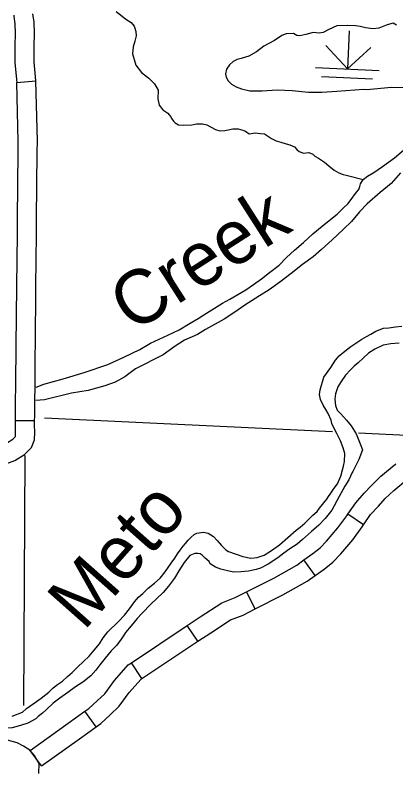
# Model space of a CAD drawing. Extents: x 1196286 to 1268366, y 2040822 to 2082115.
# Drawn here: x 1232639 to 1233761, y 2054453 to 2056680 of the extents above; entities that cross this region are included whole.
import ezdxf

# ---------------------------------------------------------------- set-up
doc = ezdxf.new("R2010")
doc.units = 0
for name, color, linetype in [('60', 7, 'Continuous'), ('61', 7, 'Continuous'), ('62', 7, 'Continuous'), ('Level 72', 7, 'Continuous'), ('Level 73', 7, 'Continuous'), ('Level 74', 7, 'Continuous'), ('Level 87', 7, 'Continuous')]:
    doc.layers.add(name, color=color, linetype=linetype)

msp = doc.modelspace()

# ---------------------------------------------------------------- linework, layer by layer
at = {"layer": '60'}
for points in [[(1232725.8, 2055495.4), (1233573.5, 2055454.6)], [(1233650.7, 2055450.9), (1234054.7, 2055431.4)], [(1232667.8, 2055384.5), (1232663.4, 2054648.3)]]:
    msp.add_lwpolyline(points, dxfattribs=at)
at = {"layer": '61'}
for p, q in [((1232643.7, 2056481.6), (1232699.7, 2056486.7)), ((1232696.5, 2055486.6), (1232640.2, 2055486.5)), ((1233665.6, 2055180), (1233619.2, 2055211.9)), ((1233522.7, 2055031.3), (1233489.9, 2055077)), ((1233346.3, 2054932.7), (1233321, 2054983)), ((1233177.4, 2054837.6), (1233146.1, 2054884.4)), ((1233012.7, 2054727.6), (1232981.5, 2054774.4)), ((1232877.4, 2054585.9), (1232844.7, 2054631.6)), ((1232716.2, 2054470.8), (1232683.5, 2054516.7))]:
    msp.add_line(p, q, dxfattribs=at)
for points in [[(1232634.9, 2056679.9), (1232635.1, 2056676.4), (1232638.5, 2056654.6), (1232639.5, 2056625.8), (1232638.6, 2056590.3), (1232638.3, 2056539.8), (1232643.7, 2056481.6)], [(1232699.7, 2056486.7), (1232694.6, 2056542.2), (1232694.9, 2056589.5), (1232695.7, 2056626.1), (1232694.6, 2056659.9), (1232691.1, 2056682.4), (1232691, 2056683.3)], [(1232528, 2055367.5), (1232529.4, 2055367.4), (1232550.4, 2055361.4), (1232577.7, 2055356.9), (1232607.1, 2055358.1), (1232638.3, 2055369.8), (1232666.7, 2055387.6), (1232687.7, 2055407.6), (1232695.6, 2055430.8), (1232696.6, 2055453.1), (1232696.5, 2055474)], [(1232530.4, 2055423.7), (1232538.5, 2055423.3), (1232562.8, 2055416.3), (1232581.1, 2055413.3), (1232595.8, 2055413.9), (1232613.2, 2055420.5), (1232632, 2055432.3), (1232639, 2055438.9), (1232639.8, 2055441.3), (1232640.3, 2055454.2), (1232640.3, 2055473.8)], [(1232640.3, 2055473.8), (1232640.2, 2055486.5)], [(1232696.5, 2055474), (1232696.5, 2055486.6)], [(1233619.2, 2055211.9), (1233642.2, 2055245.3), (1233667.6, 2055273), (1233688.5, 2055296.3), (1233716.7, 2055323.6), (1233760.6, 2055360)], [(1233665.6, 2055180), (1233686.3, 2055210.2), (1233709.3, 2055235.2), (1233729, 2055257.3), (1233754.3, 2055281.6), (1233796.6, 2055316.7)], [(1233489.9, 2055077), (1233515.6, 2055095.5), (1233537.5, 2055112.1), (1233556.4, 2055132.1), (1233589.9, 2055171.3), (1233615.7, 2055206.7), (1233619.2, 2055211.9)], [(1233522.7, 2055031.3), (1233549, 2055050.2), (1233575.3, 2055070.1), (1233598.3, 2055094.5), (1233634.1, 2055136.4), (1233661.6, 2055174.2), (1233665.6, 2055180)], [(1233321, 2054983), (1233401.5, 2055023.6), (1233468.9, 2055061.9), (1233489.9, 2055077)], [(1233346.3, 2054932.7), (1233428.1, 2054974), (1233499.3, 2055014.5), (1233522.7, 2055031.3)], [(1233146.1, 2054884.4), (1233184.3, 2054909.8), (1233247.9, 2054950.7), (1233287.6, 2054966.1), (1233321, 2054983)], [(1233177.4, 2054837.6), (1233215.1, 2054862.8), (1233273.5, 2054900.3), (1233310.5, 2054914.7), (1233346.3, 2054932.7)], [(1232981.5, 2054774.4), (1233146.1, 2054884.4)], [(1233012.7, 2054727.6), (1233177.4, 2054837.6)], [(1232844.7, 2054631.6), (1232856.4, 2054640), (1232881, 2054661.9), (1232903.1, 2054683.2), (1232931.3, 2054722.5), (1232971.8, 2054768), (1232981.5, 2054774.4)], [(1232877.4, 2054585.9), (1232891.5, 2054596), (1232919.3, 2054620.7), (1232945.8, 2054646.2), (1232975.3, 2054687.3), (1233009, 2054725.2), (1233012.7, 2054727.6)], [(1232683.5, 2054516.7), (1232795.5, 2054596.5), (1232844.7, 2054631.6)], [(1232716.2, 2054470.8), (1232828.2, 2054550.7), (1232877.4, 2054585.9)]]:
    msp.add_lwpolyline(points, dxfattribs=at)
at = {"layer": '62'}
for points in [[(1232936.7, 2056691.1), (1232954.8, 2056677.3), (1232964.8, 2056668.5), (1232980.4, 2056658.1), (1232989.7, 2056647.5), (1232990.7, 2056644.1), (1232994.3, 2056631.6), (1232995.3, 2056619.2), (1232992.1, 2056603.4), (1232987, 2056586.2), (1232984.8, 2056565.6), (1232994.1, 2056532.7), (1233011.4, 2056511.4), (1233032.9, 2056494.2), (1233049.5, 2056478.2), (1233060.5, 2056459.6), (1233059.8, 2056433.3), (1233063.7, 2056415.5), (1233074, 2056401.5), (1233088.8, 2056391.1), (1233096.9, 2056381.2), (1233101, 2056374.4), (1233105.4, 2056368.3), (1233110.2, 2056363), (1233120.2, 2056357.2), (1233133.7, 2056355.9), (1233159.5, 2056357.1), (1233174.2, 2056359.9), (1233191, 2056360.4), (1233203.7, 2056357.6), (1233216.8, 2056350.6), (1233229.4, 2056343.7), (1233242.1, 2056339.7), (1233256.3, 2056340.3), (1233266.8, 2056342.4), (1233280, 2056345.6), (1233284.5, 2056345.5), (1233296.5, 2056345.8), (1233309.9, 2056341.8), (1233317.7, 2056338.3), (1233328.9, 2056330.3), (1233346.5, 2056333.4), (1233361.8, 2056331.7), (1233373.4, 2056330.8), (1233385.7, 2056323.1), (1233394.2, 2056317.3), (1233407.6, 2056310.4), (1233421.4, 2056306.4), (1233437.1, 2056301.7), (1233447.9, 2056298.5), (1233461.7, 2056292.3), (1233468.7, 2056284.7), (1233475.4, 2056278.6), (1233488.4, 2056273.5), (1233503.8, 2056275.6), (1233515.7, 2056271.3), (1233522, 2056265.2), (1233532.4, 2056259), (1233550.2, 2056247.8), (1233562.8, 2056236.4), (1233578.8, 2056223.8), (1233592.9, 2056216), (1233605.6, 2056211.4)], [(1232700.5, 2055585.7), (1232724, 2055593.7), (1232780.4, 2055609.8), (1232842.1, 2055628.5), (1232911.7, 2055652), (1232958.9, 2055673.9), (1233006.4, 2055696.6), (1233037.7, 2055714.9), (1233063.3, 2055726.2), (1233088.6, 2055738.3), (1233122.5, 2055754), (1233155, 2055773.5), (1233178.4, 2055787.8), (1233195, 2055797.7), (1233249.5, 2055832.7), (1233271.3, 2055844.1), (1233295.5, 2055857.7), (1233318.9, 2055872), (1233341.6, 2055887.8), (1233365, 2055904.1), (1233388.5, 2055922.5), (1233416.9, 2055944.7), (1233438.9, 2055966.6), (1233461.7, 2055988.5), (1233488.2, 2056011.4), (1233516.3, 2056036.6), (1233543.9, 2056059.2), (1233564.4, 2056075.8), (1233587.5, 2056094.7), (1233604.2, 2056111), (1233619.8, 2056125.4), (1233633.9, 2056144.4), (1233644.9, 2056159.3), (1233651.4, 2056166.7), (1233654.2, 2056175.7), (1233656.1, 2056183.6), (1233664.2, 2056196.3), (1233677.4, 2056206.6), (1233695.5, 2056217.3), (1233720.9, 2056235), (1233756.1, 2056260), (1233783, 2056282.6)], [(1233773.8, 2056216.2), (1233747.2, 2056184.6), (1233714.2, 2056157.6), (1233675.9, 2056124.6), (1233653.5, 2056101.6), (1233629.5, 2056073), (1233605.2, 2056048.9), (1233573, 2056018.5), (1233541.1, 2055990.4), (1233516.5, 2055968.9), (1233485.9, 2055946.4), (1233451.8, 2055919.4), (1233418.5, 2055894.7), (1233387.8, 2055871.8), (1233358.4, 2055854.1), (1233316, 2055826.2), (1233286.2, 2055806.3), (1233255.2, 2055785.6), (1233200.1, 2055754.8), (1233176.7, 2055740.5), (1233138.2, 2055723.3), (1233110.6, 2055706.4), (1233075.5, 2055680.9), (1232993.2, 2055639.2), (1232962.6, 2055615.2), (1232933.5, 2055600.2), (1232903, 2055588.9), (1232854.1, 2055575.3), (1232805, 2055567.4), (1232725.7, 2055548.5), (1232700.2, 2055546)], [(1233605.6, 2056211.4), (1233614.1, 2056209), (1233621.6, 2056207.4), (1233664.2, 2056196.3)], [(1232961, 2054914.6), (1232975.8, 2054932.9), (1232991.1, 2054953.7), (1233002.9, 2054967.1), (1233015, 2054978.6), (1233030.9, 2054993.4), (1233049.1, 2055008.9), (1233065.8, 2055023.7), (1233081.4, 2055042.3), (1233099, 2055067.7), (1233109.7, 2055082.6), (1233117.7, 2055095.2), (1233125.4, 2055105.6), (1233134.5, 2055117.6), (1233141, 2055125.4), (1233149, 2055135.4), (1233157.7, 2055144.3), (1233166.4, 2055151.3), (1233174.4, 2055155.7), (1233193.9, 2055158.9), (1233207.3, 2055155.7), (1233222.9, 2055146), (1233234.4, 2055133.8), (1233246.9, 2055119.8), (1233256.9, 2055109.5), (1233259.5, 2055106.8), (1233267.6, 2055101.8), (1233309.4, 2055087.3), (1233333.3, 2055082.5), (1233352.1, 2055083.7), (1233373.1, 2055090.6), (1233394.3, 2055104.6), (1233417.4, 2055121.2), (1233467, 2055164.5), (1233478.4, 2055173.7), (1233492, 2055185.2), (1233502.6, 2055194.8), (1233516.3, 2055208.2), (1233528.8, 2055219.6), (1233535.7, 2055228.9), (1233557, 2055255.7), (1233560.1, 2055260.9), (1233569.3, 2055273.6), (1233578.8, 2055288.1), (1233588.7, 2055300.4), (1233598.4, 2055323.6), (1233603.5, 2055341.6), (1233606.7, 2055352.8), (1233609.1, 2055366.3), (1233610.2, 2055390.4), (1233605.5, 2055406.6), (1233597.6, 2055427.8), (1233586.6, 2055448.6), (1233579, 2055464.1), (1233572.4, 2055478.1), (1233569.9, 2055487.9), (1233560.8, 2055508), (1233554.2, 2055519.4), (1233546.9, 2055532.6), (1233538.5, 2055549.3), (1233535.7, 2055563.6), (1233537.4, 2055577.1), (1233548.8, 2055614.6), (1233569.4, 2055643.3), (1233583.2, 2055664.5), (1233593.5, 2055677.5), (1233609.8, 2055691.2), (1233627.9, 2055705.3), (1233642.7, 2055714.8), (1233660.8, 2055726.6), (1233674, 2055734.3), (1233686.5, 2055741.7), (1233701.2, 2055750.5), (1233723.8, 2055758.5), (1233739.5, 2055760.1), (1233759.4, 2055763.2), (1233778.6, 2055764.5)], [(1233770.4, 2055714.9), (1233745.7, 2055713), (1233723.5, 2055708.8), (1233699, 2055697.1), (1233679.7, 2055685), (1233663.8, 2055670.2), (1233649.7, 2055656.4), (1233637.6, 2055647.2), (1233627, 2055636.5), (1233612.5, 2055620.5), (1233599.6, 2055601.9), (1233589.6, 2055585.8), (1233583, 2055565.2), (1233580.5, 2055549.9), (1233582.5, 2055531.8), (1233587.9, 2055517.8), (1233598.6, 2055506.7), (1233614.9, 2055488.1), (1233629.3, 2055471.7), (1233643.9, 2055447.8), (1233655.9, 2055418.7), (1233662, 2055400.6), (1233651.9, 2055372.9), (1233633.8, 2055337), (1233631.9, 2055334.4), (1233621.9, 2055313.1), (1233610.4, 2055293.7), (1233593.5, 2055263.1), (1233572, 2055223.6), (1233552.1, 2055198.6), (1233533.5, 2055179), (1233511.9, 2055160.8), (1233485.4, 2055136.8), (1233469.8, 2055123.8), (1233447.9, 2055109.8), (1233430.9, 2055096.5), (1233413.1, 2055082.9), (1233384.4, 2055064.5), (1233362.1, 2055053.1), (1233349, 2055048.4), (1233326.4, 2055043.4), (1233304.7, 2055041.9), (1233282.6, 2055041), (1233260.9, 2055045.9), (1233244.8, 2055049.5), (1233229.2, 2055055.7), (1233213.2, 2055065.3), (1233210.7, 2055072.1), (1233198.5, 2055081.7), (1233190.3, 2055090.8), (1233184.4, 2055094.7), (1233177.7, 2055095.5), (1233168.3, 2055096), (1233154, 2055089.5), (1233137.2, 2055069.4), (1233121.5, 2055044.4), (1233108.9, 2055022.8), (1233091.3, 2054999.3), (1233075, 2054980.7), (1233055.6, 2054962.6), (1233039.7, 2054947.8), (1233012.3, 2054919.2), (1232998.3, 2054904.3), (1232980.8, 2054883.5), (1232964.4, 2054863.4), (1232961.3, 2054858.2), (1232951.4, 2054843.7), (1232938.8, 2054826.2), (1232922.1, 2054809.9), (1232903.8, 2054787.9), (1232888.9, 2054767.8), (1232876.3, 2054752.2), (1232861.9, 2054735.9), (1232838, 2054717), (1232816.9, 2054703.4), (1232794.6, 2054687.2), (1232770.3, 2054669.8), (1232751.4, 2054655.8), (1232731.7, 2054637.3), (1232719.2, 2054626.2), (1232706.7, 2054615.8), (1232701, 2054610.6)], [(1232672.9, 2054639.5), (1232702, 2054659.9), (1232716, 2054670.2), (1232738, 2054688), (1232749.8, 2054699.5), (1232760.7, 2054708), (1232778.1, 2054720.1), (1232793.3, 2054733.8), (1232807, 2054745.3), (1232822.5, 2054761.6), (1232840, 2054777.9), (1232857.1, 2054793.9), (1232871.9, 2054811), (1232887.1, 2054830.3), (1232898.6, 2054848.2), (1232912.3, 2054865.7), (1232943.5, 2054895.3), (1232961, 2054914.6)], [(1232672.9, 2054639.5), (1232659.8, 2054628.4), (1232629.2, 2054616.5)], [(1232548.9, 2054615.9), (1232555.5, 2054607.6), (1232570.3, 2054594.4), (1232589.5, 2054588.1), (1232614.5, 2054583.1), (1232631.5, 2054583.9), (1232656.1, 2054590.7), (1232677.5, 2054597.7), (1232701, 2054610.6)]]:
    msp.add_lwpolyline(points, dxfattribs=at)
at = {"layer": 'Level 72'}
for points in [[(1232648.1, 2056278.8), (1232648.4, 2056308.6), (1232643.6, 2056481.6)], [(1232704.3, 2056278.2), (1232704.6, 2056309.1), (1232699.7, 2056486.7)], [(1232646.1, 2056080.8), (1232648.1, 2056278.8)], [(1232702.3, 2056080.2), (1232704.3, 2056278.2)], [(1232644.1, 2055882.8), (1232645.7, 2056036), (1232646.1, 2056080.8)], [(1232700.4, 2055882.2), (1232701.9, 2056035.5), (1232702.3, 2056080.2)], [(1232642.2, 2055684.8), (1232642.4, 2055706.8), (1232644.1, 2055882.8)], [(1232698.4, 2055684.3), (1232698.6, 2055706.2), (1232700.4, 2055882.2)], [(1232640.2, 2055486.7), (1232640.3, 2055500.3), (1232640.5, 2055516.9), (1232641.5, 2055616.6), (1232642.2, 2055684.8)], [(1232696.5, 2055486.4), (1232696.6, 2055499.8), (1232696.7, 2055516.4), (1232697.7, 2055616), (1232698.4, 2055684.3)]]:
    msp.add_lwpolyline(points, dxfattribs=at)
at = {"layer": 'Level 73'}
for p, q in [((1233622.8, 2056633.9), (1233618, 2056521.5)), ((1233618, 2056521.5), (1233554.6, 2056590.6)), ((1233618, 2056521.5), (1233687.1, 2056584.9)), ((1233524.3, 2056525.5), (1233711.7, 2056517.5)), ((1233542, 2056499.2), (1233691.8, 2056492.7))]:
    msp.add_line(p, q, dxfattribs=at)
at = {"layer": 'Level 74'}
for points in [[(1233762.5, 2056650.3), (1233752.8, 2056656.1), (1233734.8, 2056651.8), (1233710.6, 2056641.2), (1233693.8, 2056639.2), (1233671.3, 2056642.9), (1233655.7, 2056646.5), (1233641.4, 2056648.2), (1233619.4, 2056649.6), (1233586.4, 2056648.6), (1233563, 2056637.3), (1233546, 2056629.2), (1233535.1, 2056626.7)], [(1233535.1, 2056626.7), (1233517.2, 2056629.2), (1233495, 2056623.2), (1233478.1, 2056618.9), (1233468.8, 2056620.5), (1233459.1, 2056625.5), (1233437.7, 2056625.1), (1233424.2, 2056620), (1233403.4, 2056605.6), (1233372.1, 2056588.8), (1233350.1, 2056572.1), (1233327.1, 2056559.3), (1233304.9, 2056552.5), (1233293.2, 2056549.2), (1233281.2, 2056543.8), (1233270.9, 2056534.1), (1233262.1, 2056520.7), (1233259, 2056506.8), (1233260.3, 2056497.4), (1233266.5, 2056486.8), (1233276.5, 2056477.3), (1233289.9, 2056468.8), (1233305.9, 2056463), (1233330.2, 2056457.3), (1233366.5, 2056457.6), (1233411.1, 2056460), (1233454.9, 2056457.9), (1233502.8, 2056453.1), (1233542.9, 2056453.3), (1233586.8, 2056456.4), (1233665.9, 2056462.5), (1233674.9, 2056461.6), (1233747.3, 2056468.1), (1233782.1, 2056466.9)]]:
    msp.add_lwpolyline(points, dxfattribs=at)
at = {"layer": 'Level 87'}
msp.add_lwpolyline([(1232709.1, 2054448.5), (1232710.2, 2054478.2), (1232695.6, 2054501.2), (1232682.7, 2054516.8), (1232663.2, 2054529.2), (1232645.4, 2054538.4), (1232616.4, 2054546.8)], dxfattribs=at)

# ---------------------------------------------------------------- texts
at = {"layer": '62'}
for s, rotation, p in [('Creek', 32.6483, (1232985.3, 2055743)), ('Meto', 48.4938, (1232841.3, 2054865.6))]:
    msp.add_text(s, height=158.4, rotation=rotation, dxfattribs=at).set_placement(p)

doc.saveas('drawing.dxf')
